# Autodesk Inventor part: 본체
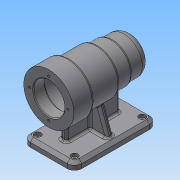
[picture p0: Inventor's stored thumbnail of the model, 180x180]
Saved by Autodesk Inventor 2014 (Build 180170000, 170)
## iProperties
Created: 2016-06
Part Number: 본체
Material: 일반
Document SubType Name: Modeling
Designer: NET
Density: 1 g/cm^3
Appearance: 기본값
Author: NET
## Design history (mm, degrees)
sketch "스케치1"
  geometry: C1 r 25 at (0, 0); 1 further point
  constraints: 1 centre point, 1 coincident
  dimensions: "d1" = 50 diameter of C1
extrude "돌출1" new body sketch "스케치1" stored distance "d2" = 25; taper "d3" = 0 deg
sketch "스케치2"
  geometry: C1 r 25 at (0, 0) reference; C2 r 27 at (0, 0)
  constraints: 1 centre point, 1 coincident
  dimensions: "d4" = 54 diameter of C2
extrude "돌출2" join sketch "스케치2" distance "d5" = 20; taper "d6" = 0 deg
sketch "스케치3"
  geometry: C1 r 27 at (0, 0) reference; C2 r 30 at (0, 0)
  constraints: 1 centre point, 1 coincident
  dimensions: "d7" = 60 diameter of C2
extrude "돌출3" join sketch "스케치3" distance "d8" = 39; taper "d9" = 0 deg
sketch "스케치4"
  geometry: C1 r 30 at (0, 0) reference; C2 r 34 at (0, 0)
  constraints: 1 centre point, 1 coincident
  dimensions: "d10" = 68 diameter of C2
extrude "돌출4" join sketch "스케치4" distance "d11" = 28; taper "d12" = 0 deg
sketch "스케치6"
  geometry: L1 (12.5, -25)-(12.5, 25) reference; L2 (-99.5, 34)-(-99.5, -34) reference; L3 (-99.5, 0)-(12.5, 0); L4 (-99.5, 21)-(-84.5, 21); L5 (-84.5, 21)-(-84.5, 0); L6 (-84.5, 0)-(-84.5, 21); L7 (-81.5, 24)-(-33.5, 24); L8 (-30.5, 21)-(-30.5, 0); L9 (-30.5, 21)-(-18.8, 21); L10 (-18.5, 20.7)-(-18.5, 0); L11 (-18.5, 17.5)-(-0.8, 17.5); L12 (-0.5, 17.2)-(-0.5, 0); L13 (3.5, 0)-(3.5, 15.7); L14 (3.2, 16)-(-0.5, 16); L15 (6.5, 0)-(6.5, 7.5); L16 (3.5, 10.5)-(3.5, 10.5); A1 r 3 centre (3.5, 7.5) between (6.5, 7.5) and (3.5, 10.5); A2 r 0.3 centre (3.2, 15.7) between (3.5, 15.7) and (3.2, 16); A3 r 0.3 centre (-0.8, 17.2) between (-0.5, 17.2) and (-0.8, 17.5); A4 r 0.3 centre (-18.8, 20.7) between (-18.5, 20.7) and (-18.8, 21); A5 r 3 centre (-33.5, 21) between (-30.5, 21) and (-33.5, 24); A6 r 3 centre (-81.5, 21) between (-81.5, 24) and (-84.5, 21); 1 further point
  constraints: 28 end point, 12 point on circle, 12 tangent, 11 perpendicular, 11 point on line, 6 centre point, 3 equal radius, 2 midpoint, 1 collinear, 1 parallel
  dimensions: "d13" = 42 diameter of L4 L3; "d15" = 32 diameter of L14 L3; "d16" = 35 diameter of L11 L3; "d17" = 42 diameter of L9 L3; "d18" = 48 diameter of L7 L3; "d24" = 15 distance between parallel lines of L2 L5; "d25" = 54 distance between parallel lines of L8 L5; "d26" = 12 distance between parallel lines of L10 L8; "d27" = 18 distance between parallel lines of L12 L10; "d29" = 4 distance between parallel lines of L12 L13; "d30" = 3 distance between parallel lines of L13 L15; "d31" = 21 diameter of L16 L3; "d32" = 3 radius of A1; "d33" = 0.3 radius of A2; "d34" = 3 radius of A5
revolve "회전1" sketch "스케치6" stored, may be unused: angle "d35" = 90 deg
chamfer "모따기1" distance "d36" = 1; stored, may be unused: second distance "d37" = 2, angle "d38" = 45 deg
sketch "스케치7" dims "d39" = 52
  geometry: L1 (0, 0)-(0, 26); C1 r 22 at (0, 0) reference
  constraints: 2 end point, 1 coincident, 1 vertical, 1 vertical alignment, 2 other
hole "구멍1" sketch "스케치7" at (0, 26) diameter "d40" = 3.242; stored, may be unused: countersink angle "d44" = 90 deg, drill point angle "d46" = 118 deg; dims "d41" = 8, "d42" = 4, "d43" = 2, "d45" = 11
fillet "모깎기1" dims "d50" = 10
fillet "모깎기2" dims "d51" = 3
node "작업 평면1"
sketch "스케치8"
  geometry: L1 (-35, -99.5)-(35, -99.5); L2 (35, -99.5)-(35, 12.5); L3 (35, 12.5)-(-35, 12.5); L4 (-35, 12.5)-(-35, -99.5); L5 (-34, -99.5)-(34, -99.5) reference; L6 (-15, 12.5)-(15, 12.5) reference; L7 (0, -99.5)-(0, 12.5); 4 further points
  constraints: 10 end point, 5 midpoint, 2 parallel, 1 horizontal, 1 horizontal alignment, 1 perpendicular, 1 vertical alignment
  dimensions: "d53" = 112 distance of L3.end L1.start; "d54" = 70 distance of L1.start L1.end
extrude "돌출5" join sketch "스케치8" distance "d55" = 10; taper "d56" = 0 deg
fillet "모깎기10" dims "d89" = 10
chamfer "모따기2" distance "d57" = 4; stored, may be unused: second distance "d58" = 2, angle "d59" = 45 deg
sketch "스케치11"
  geometry: L1 (-4, -79.5)-(4, -79.5); L2 (4, -79.5)-(4, -7.5); L3 (4, -7.5)-(-4, -7.5); L4 (-4, -7.5)-(-4, -79.5); L5 (25, 12.5)-(-25, 12.5) reference; L6 (-25, -99.5)-(25, -99.5) reference; 6 further points
  constraints: 8 end point, 2 parallel, 1 horizontal, 1 midpoint, 1 perpendicular, 1 vertical alignment
  dimensions: "d63" = 8 distance between parallel lines of L2 L4; "d64" = 20 distance between parallel lines of L5 L3; "d65" = 20 distance between parallel lines of L6 L1
extrude "돌출6" join sketch "스케치11" stored distance "d66" = 10; taper "d67" = 0 deg
node "작업 평면2"
sketch "스케치16"
  geometry: L1 (-25, -60)-(25, -60) reference; L2 (-31, -60)-(-25, -60) reference; L3 (25, -60)-(31, -60) reference; L4 (-15.306, -25.122)-(-28, -60); L5 (-15.306, -25.122)-(15.306, -25.122); L6 (-35, -70)-(-35, -64) reference; L7 (15.306, -25.122)-(28, -60); L8 (35, -64)-(35, -70) reference; L9 (-28, -60)-(28, -60); A1 r 30 centre (0, 0) between (4, -29.732) and (-4, -29.732) reference; 1 further point
  constraints: 8 end point, 2 point on line, 1 parallel, 1 perpendicular
  dimensions: "d90" = 7 distance from line of L6 L4.end; "d91" = 7 distance from line of L8 L7.end; "d92" = 110 deg angle of L2 L4; "d93" = 110 deg angle of L3 L7; "d94" = 30.611 distance of L4.start L5.end
extrude "돌출8" join sketch "스케치16" stored distance "d95" = 8; taper "d96" = 0 deg
fillet "모깎기11" dims "d97" = 3
fillet "모깎기12" dims "d98" = 3
fillet "모깎기13" dims "d99" = 3
fillet "모깎기14" dims "d100" = 3
fillet "모깎기15" dims "d101" = 3
sketch "스케치18"
  geometry: C1 r 4.5 at (-25, -89.5); C2 r 4.5 at (25, -89.5); C3 r 4.5 at (25, 2.5); C4 r 4.5 at (-25, 2.5); A1 r 6 centre (25, 2.5) between (31, 2.5) and (25, 8.5) reference; A2 r 6 centre (-25, 2.5) between (-25, 8.5) and (-31, 2.5) reference; A3 r 6 centre (-25, -89.5) between (-31, -89.5) and (-25, -95.5) reference; A4 r 6 centre (25, -89.5) between (25, -95.5) and (31, -89.5) reference; 1 further point
  constraints: 4 centre point, 4 coincident
  dimensions: "d102" = 9 diameter of C1; "d103" = 9 diameter of C2; "d104" = 9 diameter of C3; "d105" = 9 diameter of C4
extrude "돌출9" cut sketch "스케치18" distance "d106" = 4; taper "d107" = 0 deg
sketch "스케치19"
  geometry: C1 r 4.5 at (0, 0) reference; C2 r 4.5 at (-50, 0) reference; C3 r 4.5 at (-50, 92) reference; C4 r 4.5 at (0, 92) reference; C5 r 4.5 at (0, 92) reference; C6 r 2.5 at (-50, 0); C7 r 2.5 at (0, 0); C8 r 2.5 at (0, 92); C9 r 2.5 at (-50, 92); 1 further point
  constraints: 4 centre point, 4 coincident
  dimensions: "d108" = 5 diameter of C6; "d109" = 5 diameter of C7; "d110" = 5 diameter of C8; "d111" = 5 diameter of C9
extrude "돌출10" cut sketch "스케치19" stored distance "d112" = 4; taper "d113" = 0 deg
node "작업 평면4"
sketch "스케치21"
  geometry: L1 (99.5, -34)-(99.5, 34) reference; 2 further points
  constraints: 1 horizontal alignment, 1 other
  dimensions: "d116" = 48 distance from line of L1 point (51.5, 0)
feature "엠보싱1" sketch "스케치21" dims "d2" = 25, "d117" = 0.5, "d118" = 0
node "솔리드1"
pattern_circular "원형 패턴1" dims angle "d48" = 360 deg
node "투영된 루프1"
node "투영된 루프2"
